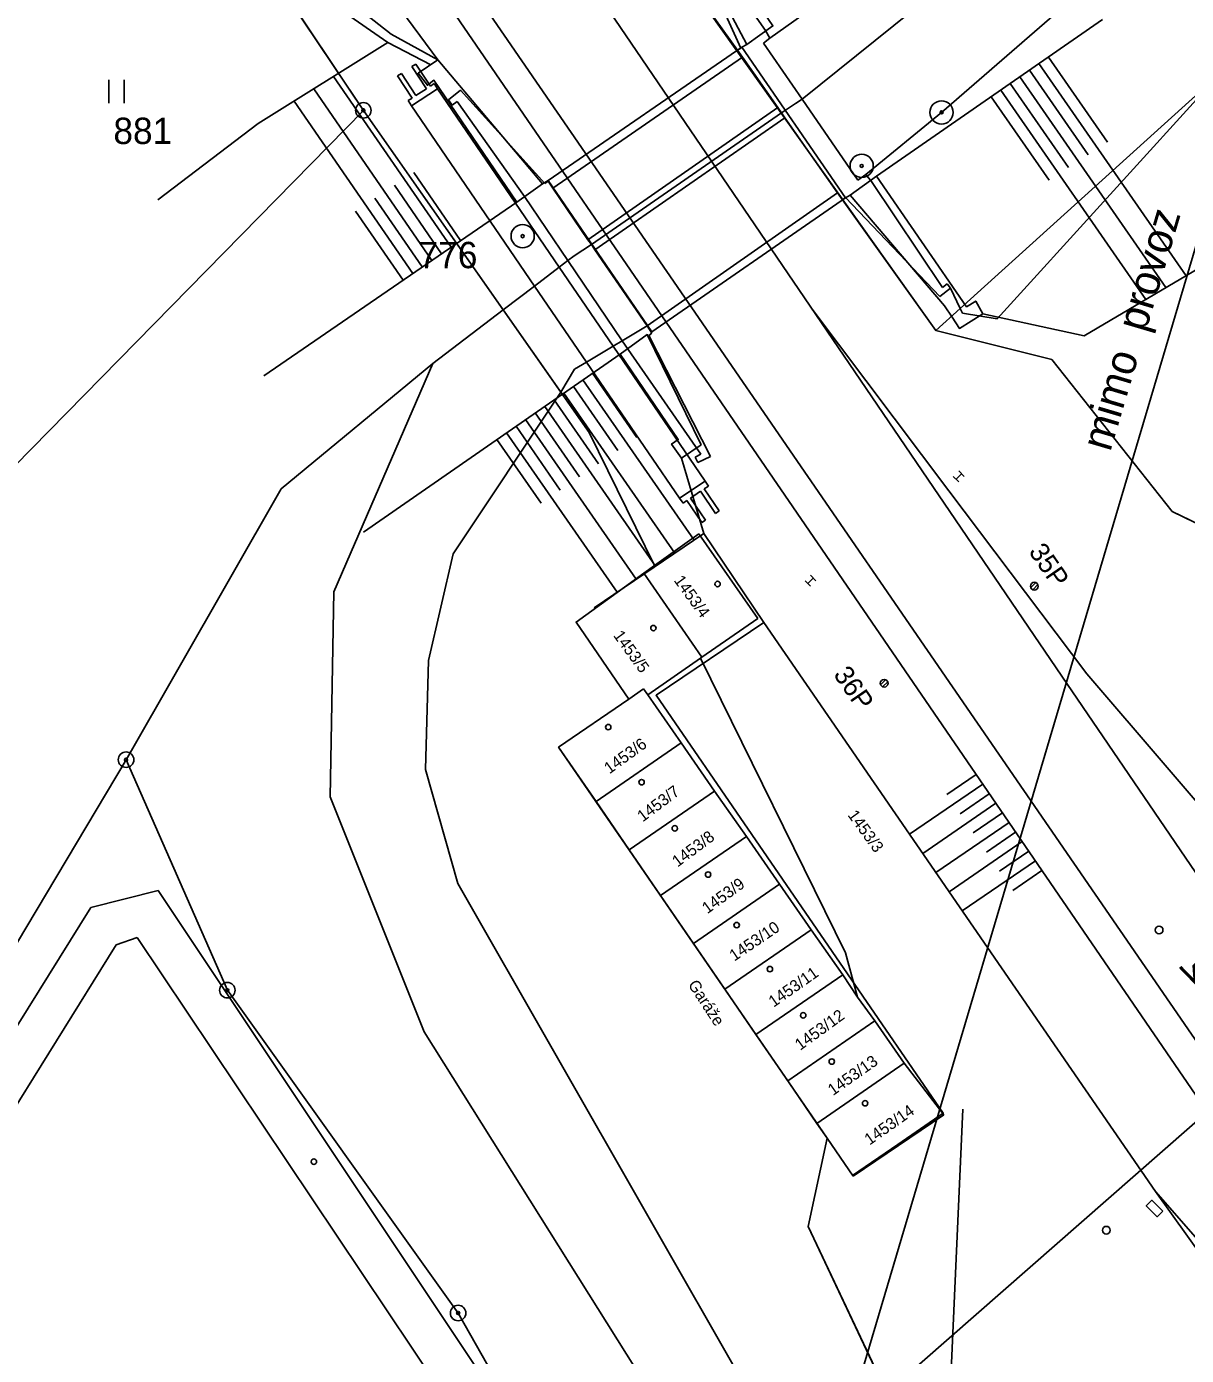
# Model space of a CAD drawing. Extents: x -469926 to -462499, y -1098642 to -1092733.
# Drawn here: x -465590.7 to -465515.9, y -1094927.6 to -1094841.9 of the extents above; entities that cross this region are included whole.
import ezdxf

# ---------------------------------------------------------------- set-up
doc = ezdxf.new("R2010")
doc.units = 0
for name, color, linetype in [('Vrstva 1', 7, 'Continuous'), ('Vrstva 10', 7, 'Continuous'), ('Vrstva 11', 7, 'Continuous'), ('Vrstva 12', 7, 'Continuous'), ('Vrstva 13', 7, 'Continuous'), ('Vrstva 14', 7, 'Continuous'), ('Vrstva 15', 7, 'Continuous'), ('Vrstva 24', 7, 'Continuous'), ('Vrstva 25', 7, 'Continuous'), ('Vrstva 28', 7, 'Continuous'), ('Vrstva 4', 7, 'Continuous'), ('Vrstva 48', 7, 'Continuous'), ('Vrstva 50', 7, 'Continuous'), ('Vrstva 6', 7, 'Continuous'), ('Vrstva 60', 7, 'Continuous'), ('Vrstva 8', 7, 'Continuous')]:
    doc.layers.add(name, color=color, linetype=linetype)

msp = doc.modelspace()

# ---------------------------------------------------------------- linework, layer by layer
at = {"layer": 'Vrstva 1'}
for p, q in [((-465601.89, -1094798.03), (-465568.94, -1094847.26)), ((-465544.81, -1094843.38), (-465550.64, -1094835.27)), ((-465540.65, -1094846.54), (-465527.9, -1094836.26)), ((-465544.49, -1094843.83), (-465544.81, -1094843.38)), ((-465542.22, -1094847.08), (-465544.49, -1094843.83)), ((-465530.47, -1094860.04), (-465513.71, -1094844.88)), ((-465541.07, -1094846.82), (-465540.65, -1094846.54)), ((-465607.69, -1094886.76), (-465568.94, -1094847.26)), ((-465568.94, -1094847.26), (-465559.92, -1094860.13)), ((-465541.99, -1094847.41), (-465542.22, -1094847.08)), ((-465541.99, -1094847.41), (-465541.07, -1094846.82)), ((-465541.77, -1094847.73), (-465541.99, -1094847.41)), ((-465538.37, -1094852.57), (-465541.77, -1094847.73)), ((-465538.05, -1094853.03), (-465538.37, -1094852.57)), ((-465532.03, -1094861.45), (-465538.05, -1094853.03)), ((-465564.46, -1094863.59), (-465559.92, -1094860.13)), ((-465559.92, -1094860.13), (-465556.21, -1094865.43)), ((-465532.03, -1094861.45), (-465530.47, -1094860.04)), ((-465524.56, -1094863.32), (-465532.03, -1094861.45)), ((-465564.46, -1094863.59), (-465574.24, -1094871.66)), ((-465570.85, -1094878.31), (-465564.46, -1094863.59)), ((-465516.78, -1094873.13), (-465524.56, -1094863.32)), ((-465563.16, -1094875.87), (-465556.21, -1094865.43)), ((-465556.21, -1094865.43), (-465554.38, -1094868.04)), ((-465550.16, -1094876.62), (-465554.38, -1094868.04)), ((-465574.24, -1094871.66), (-465584.24, -1094889.14)), ((-465503.18, -1094879.73), (-465516.78, -1094873.13)), ((-465547.31, -1094874.57), (-465550.16, -1094876.62)), ((-465543.51, -1094880.03), (-465547.31, -1094874.57)), ((-465564.73, -1094882.74), (-465563.16, -1094875.87)), ((-465550.85, -1094877.11), (-465550.16, -1094876.62)), ((-465555.23, -1094880.26), (-465550.85, -1094877.11)), ((-465550.85, -1094877.11), (-465547.11, -1094882.53)), ((-465571.08, -1094891.53), (-465570.85, -1094878.31)), ((-465547.11, -1094882.53), (-465543.51, -1094880.03)), ((-465551.82, -1094885.23), (-465555.23, -1094880.26)), ((-465550.6, -1094884.96), (-465547.21, -1094882.6)), ((-465547.21, -1094882.6), (-465547.11, -1094882.53)), ((-465547.21, -1094882.6), (-465537.86, -1094901.6)), ((-465564.93, -1094889.77), (-465564.73, -1094882.74)), ((-465551.82, -1094885.23), (-465550.87, -1094884.58)), ((-465550.87, -1094884.58), (-465550.6, -1094884.96)), ((-465550.6, -1094884.96), (-465548.44, -1094888.06)), ((-465556.35, -1094888.34), (-465551.82, -1094885.23)), ((-465553.94, -1094891.84), (-465556.35, -1094888.34)), ((-465553.94, -1094891.84), (-465548.44, -1094888.06)), ((-465548.44, -1094888.06), (-465546.29, -1094891.16)), ((-465597.47, -1094911.35), (-465584.24, -1094889.14)), ((-465584.24, -1094889.14), (-465577.71, -1094904.01)), ((-465562.85, -1094897.13), (-465564.93, -1094889.77)), ((-465551.81, -1094894.95), (-465546.29, -1094891.16)), ((-465546.29, -1094891.16), (-465544.24, -1094894.1)), ((-465565.02, -1094906.69), (-465571.08, -1094891.53)), ((-465551.81, -1094894.95), (-465553.94, -1094891.84)), ((-465549.78, -1094897.91), (-465544.24, -1094894.1)), ((-465544.24, -1094894.1), (-465542.1, -1094897.17)), ((-465549.78, -1094897.91), (-465551.81, -1094894.95)), ((-465542.35, -1094932.98), (-465562.85, -1094897.13)), ((-465547.66, -1094901), (-465542.1, -1094897.17)), ((-465542.1, -1094897.17), (-465540.06, -1094900.11)), ((-465547.66, -1094901), (-465549.78, -1094897.91)), ((-465545.64, -1094903.95), (-465540.06, -1094900.11)), ((-465540.06, -1094900.11), (-465538.03, -1094903.02)), ((-465545.64, -1094903.95), (-465547.66, -1094901)), ((-465537.86, -1094901.6), (-465537.07, -1094904.45)), ((-465543.63, -1094906.87), (-465538.03, -1094903.02)), ((-465538.03, -1094903.02), (-465537.07, -1094904.45)), ((-465577.71, -1094904.01), (-465562.83, -1094924.83)), ((-465543.63, -1094906.87), (-465545.64, -1094903.95)), ((-465537.07, -1094904.45), (-465535.96, -1094905.99)), ((-465541.58, -1094909.86), (-465535.96, -1094905.99)), ((-465535.96, -1094905.99), (-465534.07, -1094908.72)), ((-465550.58, -1094929.69), (-465565.02, -1094906.69)), ((-465541.58, -1094909.86), (-465543.63, -1094906.87)), ((-465539.7, -1094912.6), (-465534.07, -1094908.72)), ((-465534.07, -1094908.72), (-465531.52, -1094912.05)), ((-465539.7, -1094912.6), (-465541.58, -1094909.86)), ((-465539.04, -1094913.56), (-465539.7, -1094912.6)), ((-465531.52, -1094912.05), (-465537.36, -1094916)), ((-465540.27, -1094919.26), (-465539.04, -1094913.56)), ((-465537.36, -1094916), (-465539.04, -1094913.56)), ((-465535.19, -1094929.97), (-465540.27, -1094919.26)), ((-465562.83, -1094924.83), (-465556.1, -1094936.7))]:
    msp.add_line(p, q, dxfattribs=at)
at = {"layer": 'Vrstva 10'}
for points in [[(-465550.16, -1094876.62), (-465554.38, -1094868.04), (-465568.94, -1094847.26), (-465601.89, -1094798.03), (-465620.33, -1094764.94), (-465620.33, -1094764.94), (-465670.79, -1094691.66), (-465697.67, -1094652.61)], [(-465550.64, -1094835.27), (-465532.03, -1094861.45), (-465524.56, -1094863.32), (-465516.78, -1094873.13), (-465503.18, -1094879.73), (-465492.98, -1094877.99)], [(-465535.19, -1094929.97), (-465540.27, -1094919.26), (-465539.04, -1094913.56)]]:
    msp.add_lwpolyline(points, dxfattribs=at)
at = {"layer": 'Vrstva 11'}
for p, q in [((-465525.91, -1094878.042), (-465525.588, -1094877.719)), ((-465525.78, -1094878.177), (-465525.453, -1094877.85)), ((-465535.59, -1094884.302), (-465535.268, -1094883.979)), ((-465535.46, -1094884.437), (-465535.133, -1094884.11))]:
    msp.add_line(p, q, dxfattribs=at)
msp.add_lwpolyline([(-465539.04, -1094913.56), (-465556.35, -1094888.34), (-465551.82, -1094885.23), (-465555.23, -1094880.26), (-465550.16, -1094876.62)], dxfattribs=at)
for centre in [(-465525.68, -1094877.95), (-465535.36, -1094884.21)]:
    msp.add_circle(centre, 0.25, dxfattribs=at)
at = {"layer": 'Vrstva 12'}
for p, q in [((-465530.197, -1094870.87), (-465530.55, -1094870.517)), ((-465530.55, -1094871.223), (-465530.903, -1094870.87)), ((-465530.727, -1094871.047), (-465530.373, -1094870.693)), ((-465540.287, -1094877.777), (-465539.933, -1094877.423)), ((-465539.757, -1094877.6), (-465540.11, -1094877.247)), ((-465540.11, -1094877.953), (-465540.463, -1094877.6))]:
    msp.add_line(p, q, dxfattribs=at)
at = {"layer": 'Vrstva 13'}
for p, q in [((-465495.02, -1094894.75), (-465535.19, -1094929.97)), ((-465535.19, -1094929.97), (-465495.02, -1094894.75))]:
    msp.add_line(p, q, dxfattribs=at)
at = {"layer": 'Vrstva 14'}
msp.add_line((-465532.392, -1094959.459), (-465530.298, -1094911.68), dxfattribs=at)
msp.add_circle((-465517.633, -1094900.126), 0.25, dxfattribs=at)
at = {"layer": 'Vrstva 24'}
for centre, radius in [((-465531.66, -1094847.39), 0.75), ((-465568.94, -1094847.26), 0.5), ((-465568.94, -1094847.26), 0.1), ((-465531.66, -1094847.39), 0.1), ((-465536.81, -1094850.84), 0.75), ((-465536.81, -1094850.84), 0.1), ((-465558.67, -1094855.37), 0.75), ((-465558.67, -1094855.37), 0.1), ((-465584.24, -1094889.14), 0.5), ((-465584.24, -1094889.14), 0.1), ((-465577.71, -1094904.01), 0.5), ((-465577.71, -1094904.01), 0.1), ((-465562.83, -1094924.83), 0.5), ((-465562.83, -1094924.83), 0.1)]:
    msp.add_circle(centre, radius, dxfattribs=at)
at = {"layer": 'Vrstva 25'}
for p, q in [((-465585.36, -1094845.29), (-465585.36, -1094846.79)), ((-465584.36, -1094845.29), (-465584.36, -1094846.79))]:
    msp.add_line(p, q, dxfattribs=at)
for centre in [(-465546.1, -1094877.81), (-465550.24, -1094880.65), (-465553.15, -1094887.04), (-465551, -1094890.59), (-465548.86, -1094893.57), (-465546.71, -1094896.55), (-465544.87, -1094899.81), (-465542.73, -1094902.65), (-465540.58, -1094905.63), (-465538.74, -1094908.61), (-465536.59, -1094911.3), (-465572.13, -1094915.07)]:
    msp.add_circle(centre, 0.175, dxfattribs=at)
at = {"layer": 'Vrstva 28'}
msp.add_circle((-465521.04, -1094919.49), 0.25, dxfattribs=at)
at = {"layer": 'Vrstva 4'}
for p, q in [((-465542.73, -1094842.6), (-465530.65, -1094834.02)), ((-465547.93, -1094835.94), (-465544.6, -1094843.24)), ((-465543.01, -1094842.11), (-465547.35, -1094835.93)), ((-465523.24, -1094840.07), (-465531.66, -1094847.39)), ((-465542.73, -1094842.6), (-465543.01, -1094842.11)), ((-465543.14, -1094842.92), (-465542.73, -1094842.6)), ((-465540.65, -1094846.54), (-465543.14, -1094842.92)), ((-465556.73, -1094852.28), (-465544.49, -1094843.83)), ((-465544.6, -1094843.24), (-465544.81, -1094843.38)), ((-465566.73, -1094845.04), (-465566.48, -1094844.88)), ((-465566.48, -1094844.88), (-465565.55, -1094846.3)), ((-465565.81, -1094844.44), (-465565.56, -1094844.28)), ((-465564.88, -1094845.86), (-465565.81, -1094844.44)), ((-465565.56, -1094844.28), (-465564.62, -1094845.7)), ((-465528.07, -1094860.71), (-465513.71, -1094844.88)), ((-465565.8, -1094846.47), (-465566.73, -1094845.04)), ((-465564.62, -1094845.7), (-465564.37, -1094845.53)), ((-465564.37, -1094845.53), (-465564.15, -1094845.87)), ((-465566.05, -1094846.63), (-465565.8, -1094846.47)), ((-465565.83, -1094846.97), (-465566.05, -1094846.63)), ((-465564.15, -1094845.87), (-465565.83, -1094846.97)), ((-465565.55, -1094846.3), (-465564.88, -1094845.86)), ((-465564.15, -1094845.87), (-465556.31, -1094857.38)), ((-465562.67, -1094845.96), (-465563.45, -1094846.59)), ((-465563.45, -1094846.59), (-465563.21, -1094846.92)), ((-465557.24, -1094851.97), (-465562.67, -1094845.96)), ((-465537.05, -1094851.77), (-465540.65, -1094846.54)), ((-465565.83, -1094846.97), (-465557.9, -1094858.59)), ((-465563.21, -1094846.92), (-465562.89, -1094846.68)), ((-465562.89, -1094846.68), (-465558.55, -1094852.82)), ((-465554.46, -1094855.6), (-465542.22, -1094847.08)), ((-465554.24, -1094855.92), (-465541.99, -1094847.41)), ((-465531.66, -1094847.39), (-465536.54, -1094851.4)), ((-465554.01, -1094856.25), (-465541.77, -1094847.73)), ((-465536.54, -1094851.4), (-465537.05, -1094851.77)), ((-465536.18, -1094851.85), (-465536.54, -1094851.4)), ((-465557.03, -1094851.83), (-465557.24, -1094851.97)), ((-465556.73, -1094852.28), (-465557.03, -1094851.83)), ((-465554.46, -1094855.6), (-465556.73, -1094852.28)), ((-465550.65, -1094861.16), (-465538.37, -1094852.57)), ((-465531.59, -1094858.68), (-465536.18, -1094851.85)), ((-465558.55, -1094852.82), (-465555.75, -1094856.95)), ((-465538.05, -1094853.03), (-465537.85, -1094852.88)), ((-465537.85, -1094852.88), (-465531.77, -1094859.26)), ((-465555.35, -1094856.65), (-465554.24, -1094855.92)), ((-465554.24, -1094855.92), (-465554.46, -1094855.6)), ((-465554.24, -1094855.92), (-465554.01, -1094856.25)), ((-465555.75, -1094856.95), (-465555.35, -1094856.65)), ((-465554.01, -1094856.25), (-465550.65, -1094861.16)), ((-465557.9, -1094858.59), (-465556.31, -1094857.38)), ((-465556.31, -1094857.38), (-465555.75, -1094856.95)), ((-465556.31, -1094857.38), (-465552.84, -1094862.47)), ((-465555.75, -1094856.95), (-465552.25, -1094862.12)), ((-465559.92, -1094860.13), (-465557.9, -1094858.59)), ((-465557.9, -1094858.59), (-465554.55, -1094863.5)), ((-465531.3, -1094858.45), (-465531.59, -1094858.68)), ((-465531.08, -1094858.73), (-465531.3, -1094858.45)), ((-465531.77, -1094859.26), (-465531.08, -1094858.73)), ((-465531.08, -1094858.73), (-465530.47, -1094860.04)), ((-465530.47, -1094860.04), (-465530.32, -1094860.34)), ((-465530.32, -1094860.34), (-465528.07, -1094860.71)), ((-465552.25, -1094862.12), (-465550.65, -1094861.16)), ((-465550.65, -1094861.16), (-465550.33, -1094861.63)), ((-465550.33, -1094861.63), (-465550.54, -1094861.77)), ((-465550.54, -1094861.77), (-465546.56, -1094869.58)), ((-465554.55, -1094863.5), (-465552.84, -1094862.47)), ((-465552.84, -1094862.47), (-465552.25, -1094862.12)), ((-465552.84, -1094862.47), (-465546.91, -1094871.17)), ((-465551.86, -1094862.69), (-465552.25, -1094862.12)), ((-465547.19, -1094869.44), (-465551.86, -1094862.69)), ((-465555.32, -1094863.96), (-465554.55, -1094863.5)), ((-465554.55, -1094863.5), (-465548.55, -1094872.28)), ((-465556.21, -1094865.43), (-465555.32, -1094863.96)), ((-465547.54, -1094869.62), (-465547.19, -1094869.44)), ((-465547.37, -1094869.97), (-465547.54, -1094869.62)), ((-465546.56, -1094869.58), (-465547.37, -1094869.97)), ((-465548.55, -1094872.28), (-465546.91, -1094871.17)), ((-465546.69, -1094871.49), (-465546.96, -1094871.67)), ((-465546.91, -1094871.17), (-465546.69, -1094871.49)), ((-465548.33, -1094872.6), (-465548.55, -1094872.28)), ((-465547.2, -1094871.83), (-465547.84, -1094872.27)), ((-465547.84, -1094872.27), (-465546.88, -1094873.69)), ((-465546.24, -1094873.26), (-465547.2, -1094871.83)), ((-465546.96, -1094871.67), (-465546, -1094873.09)), ((-465548.08, -1094872.43), (-465548.33, -1094872.6)), ((-465547.11, -1094873.85), (-465548.08, -1094872.43)), ((-465546, -1094873.09), (-465546.24, -1094873.26)), ((-465546.88, -1094873.69), (-465547.11, -1094873.85)), ((-465582.18, -1094897.58), (-465586.52, -1094898.68)), ((-465556.1, -1094936.7), (-465582.18, -1094897.58)), ((-465586.52, -1094898.68), (-465600.01, -1094920.35)), ((-465584.87, -1094901.09), (-465583.53, -1094900.6)), ((-465583.53, -1094900.6), (-465560.17, -1094935.47)), ((-465597.31, -1094921.05), (-465584.87, -1094901.09))]:
    msp.add_line(p, q, dxfattribs=at)
at = {"layer": 'Vrstva 48'}
for p, q in [((-465524.767, -1094843.818), (-465520.959, -1094849.308)), ((-465526, -1094844.673), (-465522.217, -1094850.127)), ((-465525.383, -1094844.245), (-465515.894, -1094857.926)), ((-465563.287, -1094856.085), (-465570.864, -1094845.072)), ((-465527.232, -1094845.528), (-465523.474, -1094850.945)), ((-465526.616, -1094845.1), (-465517.189, -1094858.69)), ((-465564.523, -1094856.935), (-465572.137, -1094845.868)), ((-465528.464, -1094846.382), (-465524.732, -1094851.764)), ((-465527.848, -1094845.955), (-465518.485, -1094859.454)), ((-465565.759, -1094857.786), (-465573.41, -1094846.665)), ((-465562.669, -1094855.66), (-465565.692, -1094851.266)), ((-465563.905, -1094856.51), (-465566.943, -1094852.094)), ((-465565.14, -1094857.36), (-465568.193, -1094852.923)), ((-465566.377, -1094858.211), (-465569.444, -1094853.752)), ((-465554.784, -1094864.64), (-465547.612, -1094874.98)), ((-465554.168, -1094864.212), (-465551.297, -1094868.351)), ((-465556.016, -1094865.495), (-465548.854, -1094875.819)), ((-465555.401, -1094865.067), (-465552.534, -1094869.2)), ((-465557.249, -1094866.35), (-465550.098, -1094876.659)), ((-465556.633, -1094865.922), (-465553.77, -1094870.049)), ((-465558.481, -1094867.205), (-465551.341, -1094877.498)), ((-465557.866, -1094866.777), (-465555.007, -1094870.898)), ((-465559.714, -1094868.06), (-465552.584, -1094878.338)), ((-465559.098, -1094867.632), (-465556.244, -1094871.747)), ((-465560.331, -1094868.487), (-465557.481, -1094872.596)), ((-465529.427, -1094890.096), (-465531.316, -1094891.39)), ((-465529.003, -1094890.714), (-465533.723, -1094893.948)), ((-465528.156, -1094891.952), (-465532.873, -1094895.183)), ((-465528.58, -1094891.333), (-465530.467, -1094892.626)), ((-465527.732, -1094892.571), (-465529.618, -1094893.863)), ((-465527.308, -1094893.189), (-465532.023, -1094896.419)), ((-465526.46, -1094894.427), (-465531.173, -1094897.655)), ((-465526.884, -1094893.808), (-465528.77, -1094895.1)), ((-465526.036, -1094895.046), (-465527.921, -1094896.337)), ((-465525.613, -1094895.664), (-465530.323, -1094898.891)), ((-465525.189, -1094896.283), (-465527.072, -1094897.573))]:
    msp.add_line(p, q, dxfattribs=at)
at = {"layer": 'Vrstva 6'}
for p, q in [((-465521.287, -1094841.404), (-465535.847, -1094851.503)), ((-465544.224, -1094843.009), (-465544.53, -1094843.18)), ((-465557.388, -1094851.992), (-465557.03, -1094851.78)), ((-465575.354, -1094864.387), (-465559.054, -1094853.173)), ((-465537.86, -1094852.9), (-465537.554, -1094852.729)), ((-465552.39, -1094862.979), (-465568.938, -1094874.458)), ((-465548.43, -1094869.69), (-465546.99, -1094874.56)), ((-465517.87, -1094916.99), (-465500.09, -1094937.37))]:
    msp.add_line(p, q, dxfattribs=at)
for points in [[(-465542.645, -1094856.19), (-465561.38, -1094828.63), (-465575.13, -1094808.61), (-465592.17, -1094783.73), (-465605.09, -1094765.02), (-465619.31, -1094745.2), (-465646.85, -1094705.26), (-465661.57, -1094683.67), (-465677.31, -1094661.01), (-465693.87, -1094636.55), (-465698.42, -1094629.78), (-465716.18, -1094603.98), (-465733.73, -1094578.62), (-465748.29, -1094557.47), (-465768.97, -1094527.43)], [(-465434.36, -1095026.37), (-465448.49, -1095009.06), (-465466.41, -1094985.15), (-465481.4, -1094961.47), (-465496.39, -1094937.79), (-465514.47, -1094911.93), (-465541.255, -1094872.83), (-465568.04, -1094833.73), (-465581.135, -1094814.86), (-465597.23, -1094791.03), (-465612.74, -1094768.15), (-465622.568, -1094754.33), (-465641.197, -1094726.93), (-465652.461, -1094710.94), (-465670.86, -1094684.36), (-465683.59, -1094665.34), (-465705.04, -1094634.71), (-465721.42, -1094610.27), (-465739.86, -1094583.31), (-465754.366, -1094564.659), (-465741.97, -1094582.27)], [(-465564.13, -1094844.01), (-465571.24, -1094834.39), (-465584.41, -1094816.27), (-465599.38, -1094795.04), (-465608.276, -1094781.312), (-465599.73, -1094796.96), (-465596.69, -1094821.59)], [(-465564.13, -1094844.01), (-465567.154, -1094842.348), (-465572.91, -1094837.8), (-465578.106, -1094833.197), (-465597.363, -1094816.14)], [(-465597.199, -1094817.468), (-465585.424, -1094827.984), (-465573.65, -1094838.5), (-465567.36, -1094842.88), (-465564.584, -1094844.315)], [(-465567.36, -1094842.88), (-465575.72, -1094848.11), (-465582.187, -1094853.02)], [(-465529, -1094860.39), (-465522.46, -1094861.8), (-465514.19, -1094856.92), (-465509.542, -1094853.275)], [(-465542.645, -1094856.19), (-465523.91, -1094883.75), (-465506.3, -1094909.59), (-465490.33, -1094932.99), (-465474.43, -1094956.03), (-465442.6, -1095002.04), (-465429.689, -1095019.75), (-465428.49, -1095021.29), (-465416.22, -1095035.84), (-465398.611, -1095054.406), (-465391.848, -1095060.089), (-465391.38, -1095060.44), (-465363.84, -1095082.26), (-465348.99, -1095091.83), (-465330.29, -1095102.47), (-465300.84, -1095115.8), (-465286.15, -1095121.03)], [(-465493.53, -1094919.018), (-465501.96, -1094907.32), (-465522.3, -1094883.61), (-465531.18, -1094871.802), (-465540.06, -1094859.993)], [(-465537.396, -1094915.965), (-465534.473, -1094913.958), (-465531.55, -1094911.95), (-465550.07, -1094884.984), (-465543.12, -1094880.29), (-465546.99, -1094874.56), (-465554.063, -1094879.337)], [(-465324.52, -1095121.16), (-465355.228, -1095103.306), (-465366.7, -1095096.22), (-465388.26, -1095080.92), (-465407.46, -1095064.389), (-465410.74, -1095061.49), (-465438.84, -1095028.81), (-465471.05, -1094987.83), (-465484.21, -1094964), (-465501.26, -1094940.2), (-465517.87, -1094916.99), (-465530.495, -1094898.64), (-465543.12, -1094880.29)]]:
    msp.add_lwpolyline(points, dxfattribs=at)
for points in [[(-465544.224, -1094843.009), (-465549.26, -1094833.47), (-465547.858, -1094832.68), (-465547.4, -1094833.509), (-465548.008, -1094833.837), (-465542.538, -1094841.809)], [(-465557.03, -1094851.78), (-465550.33, -1094861.55), (-465537.86, -1094852.9), (-465544.53, -1094843.18)], [(-465559.054, -1094853.173), (-465564.39, -1094845.32), (-465564.812, -1094845.642), (-465565.41, -1094844.87), (-465564.13, -1094844.01), (-465557.388, -1094851.992)], [(-465535.847, -1094851.503), (-465537.554, -1094852.729), (-465531.46, -1094859.87), (-465530.985, -1094860.595), (-465530.51, -1094861.32), (-465529, -1094860.39), (-465529.46, -1094859.561), (-465530.045, -1094859.93)], [(-465547.15, -1094868.83), (-465550.636, -1094861.721), (-465552.39, -1094862.979), (-465548.64, -1094868.498), (-465549.063, -1094868.784), (-465548.43, -1094869.69)]]:
    msp.add_lwpolyline(points, close=True, dxfattribs=at)
at = {"layer": 'Vrstva 60'}
msp.add_lwpolyline([(-465597.64, -1094787.45), (-465581.093, -1094811.54), (-465566.234, -1094833.14), (-465554.41, -1094850.35), (-465547.999, -1094859.66), (-465532.57, -1094882.09), (-465512.32, -1094911.53), (-465495.08, -1094936.61), (-465478.69, -1094960.45), (-465461.05, -1094986.11), (-465447.884, -1095005.16), (-465433.628, -1095024.45), (-465420.884, -1095039.67), (-465408.48, -1095052.76), (-465395.882, -1095064.54), (-465388.083, -1095071.147)], dxfattribs=at)
at = {"layer": 'Vrstva 8'}
msp.add_line((-465555.861, -1094992.932), (-465490.935, -1094773.91), dxfattribs=at)
msp.add_lwpolyline([(-465517.402, -1094918.263), (-465517.755, -1094918.617), (-465518.462, -1094917.91), (-465518.108, -1094917.557), (-465517.402, -1094918.263)], dxfattribs=at)

# ---------------------------------------------------------------- texts
at = {"layer": 'Vrstva 11'}
for s, p in [('35P', (-465526.082, -1094875.721)), ('36P', (-465538.672, -1094883.651))]:
    msp.add_text(s, height=1.25, rotation=304.64122, dxfattribs=at).set_placement(p)
at = {"layer": 'Vrstva 15'}
msp.add_text('Garáže', height=0.75, rotation=303.16133, dxfattribs=at).set_placement((-465548.036, -1094903.646))
at = {"layer": 'Vrstva 50'}
for s, p in [('881', (-465585.058, -1094849.43)), ('776', (-465565.378, -1094857.44))]:
    msp.add_text(s, height=1.7, dxfattribs=at).set_placement(p)
for s, height, rotation, p in [('1453/4', 0.75, 306.018, (-465548.952, -1094877.581)), ('1453/5', 0.75, 306.018, (-465552.858, -1094881.134)), ('1453/6', 0.75, 35.982, (-465553.076, -1094890.092)), ('1453/7', 0.75, 36.9, (-465550.929, -1094893.189)), ('1453/3', 0.75, 306.018, (-465537.746, -1094892.718)), ('1453/8', 0.75, 36.9, (-465548.681, -1094896.101)), ('k.ú.Pudlov', 1.7, 44.06081, (-465515.215, -1094903.968)), ('1453/9', 0.75, 35.982, (-465546.763, -1094899.113)), ('1453/10', 0.75, 34.209, (-465545.02, -1094902.168)), ('1453/11', 0.75, 35.118, (-465542.486, -1094905.139)), ('1453/12', 0.75, 35.982, (-465540.777, -1094907.924)), ('1453/13', 0.75, 35.118, (-465538.662, -1094910.839)), ('1453/14', 0.75, 35.118, (-465536.303, -1094914.033))]:
    msp.add_text(s, height=height, rotation=rotation, dxfattribs=at).set_placement(p)
at = {"layer": 'Vrstva 8'}
msp.add_text('mimo  provoz', height=1.99999, rotation=73.48828, dxfattribs=at).set_placement((-465520.786, -1094869.331))

doc.saveas('drawing.dxf')
